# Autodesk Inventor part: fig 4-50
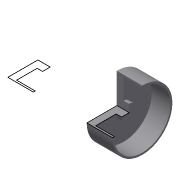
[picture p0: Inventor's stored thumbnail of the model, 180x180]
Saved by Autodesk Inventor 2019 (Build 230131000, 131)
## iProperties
Created: 2004-05
Part Number: fig 4-50
Document SubType Name: Modeling
Designer: CADCIM Technologies
Manufacturer: Standard
Standards Organization: Custom
Density: 1 g/cm^3
Material: Generic
Appearance: Default
Author: CADCIM Technologies
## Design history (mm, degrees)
sketch "Sketch1"
  geometry: L1 (30.083, 49.92)-(16.646, 49.92); L2 (16.646, 49.92)-(16.646, 17.104); L3 (16.646, 17.104)-(44.553, 17.104); L4 (44.553, 17.104)-(44.553, 19.171); L5 (44.553, 19.171)-(24.139, 19.171); L6 (24.139, 19.171)-(24.139, 41.652); L7 (24.139, 41.652)-(30.083, 41.652); L8 (30.083, 41.652)-(30.083, 49.92); L9 (116.437, 49.92)-(103, 49.92); L10 (103, 49.92)-(103, 17.104); L11 (103, 17.104)-(130.907, 17.104); L12 (130.907, 17.104)-(130.907, 19.171); L13 (130.907, 19.171)-(110.494, 19.171); L14 (110.494, 19.171)-(110.494, 41.652); L15 (110.494, 41.652)-(116.437, 41.652); L16 (116.437, 41.652)-(116.437, 49.92)
  constraints: 32 end point, 2 horizontal
revolve "Revolution1" sketch "Sketch1" stored, may be unused: angle "d0" = 270 deg
body "Solid1"
